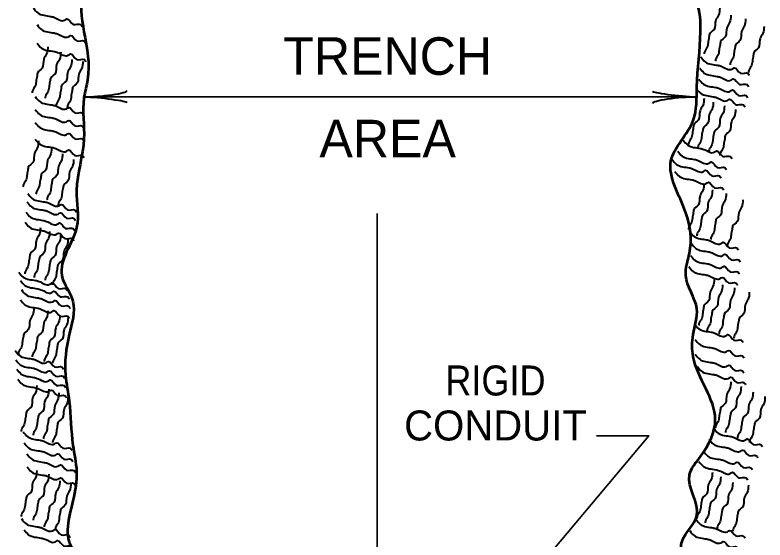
# Model space of a CAD drawing. Extents: x -617 to 238, y 23 to 567.
# Drawn here: x -260.3 to -200.2, y 290.5 to 332.5 of the extents above; entities that cross this region are included whole.
import ezdxf
from ezdxf.enums import TextEntityAlignment as Align

# ---------------------------------------------------------------- set-up
doc = ezdxf.new("R2010")
doc.units = 0
doc.header["$LTSCALE"] = 0.96
doc.layers.add('1', color=7, linetype='Continuous', lineweight=40)

msp = doc.modelspace()

# ---------------------------------------------------------------- linework, layer by layer
at = {"layer": '1', "lineweight": 35}
for p, q in [((-205.7838, 325.9777), (-254.7461, 325.9777)), ((-231.291, 269.4176), (-231.291, 316.6626))]:
    msp.add_line(p, q, dxfattribs=at)
msp.add_lwpolyline([(-224.4112, 281.1268), (-209.5319, 298.8592), (-213.7319, 298.8592)], dxfattribs=at)
at = {"layer": '1'}
for centre, major_axis, ratio, start_param, end_param in [((-253.4015, 325.7238), (2.1077, -0.2108), 0.07063, 6.2823074, 8.5597026), ((-253.4015, 325.7238), (2.1077, -0.2108), 0.07063, 6.2823074, 8.5597026), ((-253.4367, 326.3093), (-2.1428, -0.1874), 0.122415, 0.8963533, 3.1415927), ((-253.4367, 326.3093), (-2.1428, -0.1874), 0.122415, 0.8963533, 3.1415927), ((-207.0932, 325.6461), (2.1428, 0.1874), 0.122415, 0.8963533, 3.1415927), ((-207.1284, 326.2316), (2.1077, -0.2108), 0.07063, 3.1407148, 5.41811)]:
    msp.add_ellipse(centre, major_axis=major_axis, ratio=ratio, start_param=start_param, end_param=end_param, dxfattribs=at)
at = {"layer": '1', "lineweight": 53}
msp.add_spline([(-255.291, 382.6114), (-255.9281, 375.2243), (-254.7461, 372.2695), (-255.9281, 369.6102), (-255.0416, 367.2463), (-255.9281, 363.9961), (-254.7461, 361.9277), (-254.4506, 359.2684), (-254.7461, 355.1316), (-255.0416, 353.0633), (-256.2235, 351.5858), (-256.519, 350.6994), (-255.9281, 349.222), (-255.6326, 347.4491), (-255.3371, 345.3807), (-255.0416, 343.3124), (-255.0416, 340.9485), (-253.8597, 337.6982), (-254.1552, 335.6299), (-254.7461, 334.4479), (-254.7461, 331.1977), (-254.4506, 327.3564), (-254.7461, 325.879), (-254.7461, 322.6287), (-255.3371, 318.492), (-255.3371, 315.5372), (-256.519, 311.6959), (-255.6326, 309.6275), (-255.9281, 306.9682), (-256.2235, 303.7179), (-255.9281, 301.6495), (-255.6326, 298.1038), (-255.3371, 296.0354), (-255.6326, 293.6716), (-255.6326, 289.8303), (-254.7461, 288.9439), (-255.3371, 284.2162), (-255.3371, 281.5568), (-255.0416, 279.7839), (-255.6326, 276.2382), (-255.0416, 274.7608), (-255.6326, 272.1014), (-255.0416, 270.9195), (-252.6778, 268.5557), (-250.6094, 269.1466), (-248.541, 270.624), (-246.7681, 269.1466), (-244.9953, 268.8511), (-241.154, 268.8511), (-237.3127, 270.3286), (-236.1308, 269.4421), (-231.1076, 269.4421), (-226.6754, 270.0331), (-224.3116, 269.4421), (-219.2884, 270.0331), (-217.5155, 269.7376), (-212.1969, 270.0331), (-211.6059, 269.1466), (-208.0601, 269.7376), (-205.4008, 273.2834), (-205.6963, 275.3517), (-205.9918, 276.5337), (-207.7646, 282.1478), (-205.4008, 285.9891), (-206.8782, 289.2393), (-206.8782, 290.4213), (-205.6963, 292.4896), (-206.2872, 295.7399), (-205.4008, 297.2173), (-204.2189, 300.1721), (-205.9918, 305.1953), (-205.9918, 306.9682), (-205.6963, 309.0366), (-206.5827, 311.6959), (-206.2872, 313.4688), (-206.5827, 316.7191), (-207.7646, 320.8558), (-205.9918, 324.1061), (-205.6963, 326.7654), (-205.4008, 331.1977), (-205.6963, 333.5615), (-206.5827, 335.6299), (-206.5827, 337.4028), (-206.2872, 340.9485), (-207.4692, 344.4943), (-207.7646, 347.7446), (-205.6963, 350.9949), (-206.5827, 353.3587), (-206.8782, 354.8361), (-205.4008, 358.3819), (-206.5827, 361.0412), (-206.5827, 366.0644), (-206.2872, 367.8373), (-205.9918, 369.6102), (-207.1737, 372.8605), (-207.4692, 374.6334), (-207.291, 382.6114)], degree=3, dxfattribs=at)
at = {"layer": '1'}
for points in [[(-258.7864, 333.0944), (-258.4349, 332.6941), (-257.4359, 332.4265), (-257.1505, 332.3501), (-256.2943, 332.1206), (-256.1133, 332.2251), (-255.6188, 331.7868), (-255.0099, 331.7764), (-254.9054, 331.5956)], [(-203.8613, 333.1016), (-203.9639, 332.5197), (-204.1863, 332.1089), (-204.3146, 331.3813), (-204.6827, 330.9962), (-204.7082, 330.8508), (-204.7852, 330.4142), (-204.8621, 329.9777), (-205.0847, 329.567), (-205.1104, 329.4214)], [(-202.9749, 332.5107), (-203.0775, 331.9288), (-203.2999, 331.518), (-203.4282, 330.7904), (-203.7963, 330.4053), (-203.8218, 330.2599), (-203.8988, 329.8233), (-203.9757, 329.3868), (-204.1983, 328.9761), (-204.224, 328.8305)], [(-201.7929, 332.2152), (-201.8955, 331.6333), (-202.1179, 331.2225), (-202.2462, 330.4949), (-202.6143, 330.1098), (-202.6398, 329.9644), (-202.7168, 329.5278), (-202.7937, 329.0913), (-203.0163, 328.6806), (-203.042, 328.535)], [(-258.4909, 331.7648), (-258.1394, 331.3645), (-257.1404, 331.0969), (-256.855, 331.0205), (-255.9988, 330.791), (-255.8178, 330.8955), (-255.3233, 330.4572), (-254.7144, 330.4468), (-254.6099, 330.266)], [(-200.3155, 331.6242), (-200.4181, 331.0423), (-200.6405, 330.6315), (-200.7688, 329.9039), (-201.1369, 329.5188), (-201.1624, 329.3734), (-201.2394, 328.9368), (-201.3163, 328.5003), (-201.5389, 328.0896), (-201.5646, 327.944)], [(-258.4909, 330.2873), (-258.1394, 329.887), (-257.1404, 329.6194), (-256.855, 329.543), (-255.9988, 329.3135), (-255.8178, 329.418), (-255.3233, 328.9797), (-254.7144, 328.9693), (-254.6099, 328.7885)], [(-257.6388, 329.9989), (-257.7414, 329.417), (-257.9638, 329.0062), (-258.0921, 328.2786), (-258.4602, 327.8935), (-258.4857, 327.7481), (-258.5627, 327.3115), (-258.6396, 326.875), (-258.8622, 326.4643), (-258.8879, 326.3187)], [(-256.6047, 329.5557), (-256.7073, 328.9738), (-256.9297, 328.563), (-257.058, 327.8354), (-257.4261, 327.4503), (-257.4516, 327.3049), (-257.5286, 326.8683), (-257.6055, 326.4318), (-257.8281, 326.0211), (-257.8538, 325.8755)], [(-255.7183, 328.9647), (-255.8209, 328.3828), (-256.0433, 327.972), (-256.1716, 327.2444), (-256.5397, 326.8593), (-256.5652, 326.7139), (-256.6422, 326.2773), (-256.7191, 325.8408), (-256.9417, 325.4301), (-256.9674, 325.2845)], [(-205.3782, 329.1793), (-205.0267, 328.779), (-204.0277, 328.5114), (-203.7423, 328.435), (-202.8861, 328.2055), (-202.7051, 328.31), (-202.2106, 327.8717), (-201.6017, 327.8613), (-201.4972, 327.6805)], [(-254.8318, 328.817), (-254.9344, 328.2351), (-255.1568, 327.8243), (-255.2851, 327.0967), (-255.6532, 326.7116), (-255.6787, 326.5662), (-255.7557, 326.1296), (-255.8326, 325.6931), (-256.0552, 325.2824), (-256.0809, 325.1368)], [(-205.452, 328.2928), (-205.1005, 327.8925), (-204.1015, 327.6249), (-203.8161, 327.5485), (-202.9599, 327.319), (-202.7789, 327.4235), (-202.2844, 326.9852), (-201.6755, 326.9748), (-201.571, 326.794)], [(-205.5259, 327.4064), (-205.1744, 327.0061), (-204.1754, 326.7385), (-203.89, 326.6621), (-203.0338, 326.4326), (-202.8528, 326.5371), (-202.3583, 326.0988), (-201.7494, 326.0884), (-201.6449, 325.9076)], [(-205.7475, 326.6677), (-205.396, 326.2674), (-204.397, 325.9998), (-204.1116, 325.9234), (-203.2554, 325.6939), (-203.0744, 325.7984), (-202.5799, 325.3601), (-201.971, 325.3497), (-201.8665, 325.1689)], [(-258.6386, 326.0029), (-258.2871, 325.6026), (-257.2881, 325.335), (-257.0027, 325.2586), (-256.1465, 325.0291), (-255.9655, 325.1336), (-255.471, 324.6953), (-254.8621, 324.6849), (-254.7576, 324.5041)], [(-205.1171, 325.8623), (-205.2197, 325.2804), (-205.4421, 324.8696), (-205.5704, 324.142), (-205.9385, 323.7569), (-205.964, 323.6115), (-206.041, 323.1749), (-206.1179, 322.7384), (-206.3405, 322.3277), (-206.3662, 322.1821)], [(-204.3784, 325.5669), (-204.481, 324.985), (-204.7034, 324.5742), (-204.8317, 323.8466), (-205.1998, 323.4615), (-205.2253, 323.3161), (-205.3023, 322.8795), (-205.3792, 322.443), (-205.6018, 322.0323), (-205.6275, 321.8867)], [(-258.6386, 324.9687), (-258.2871, 324.5684), (-257.2881, 324.3008), (-257.0027, 324.2244), (-256.1465, 323.9949), (-255.9655, 324.0994), (-255.471, 323.6611), (-254.8621, 323.6507), (-254.7576, 323.4699)], [(-203.492, 325.2714), (-203.5946, 324.6895), (-203.817, 324.2787), (-203.9453, 323.5511), (-204.3134, 323.166), (-204.3389, 323.0206), (-204.4159, 322.584), (-204.4928, 322.1475), (-204.7154, 321.7368), (-204.7411, 321.5912)], [(-202.6055, 324.9759), (-202.7081, 324.394), (-202.9305, 323.9832), (-203.0588, 323.2556), (-203.4269, 322.8705), (-203.4524, 322.7251), (-203.5294, 322.2885), (-203.6063, 321.852), (-203.8289, 321.4413), (-203.8546, 321.2957)], [(-258.6386, 323.9345), (-258.2871, 323.5342), (-257.2881, 323.2666), (-257.0027, 323.1902), (-256.1465, 322.9607), (-255.9655, 323.0652), (-255.471, 322.6269), (-254.8621, 322.6165), (-254.7576, 322.4357)], [(-258.3776, 322.4641), (-258.4802, 321.8822), (-258.7026, 321.4714), (-258.8309, 320.7438), (-259.199, 320.3587), (-259.2245, 320.2133), (-259.3015, 319.7767), (-259.3784, 319.3402), (-259.601, 318.9295), (-259.6267, 318.7839)], [(-258.6386, 322.6048), (-258.2871, 322.2045), (-257.2881, 321.9369), (-257.0027, 321.8605), (-256.1465, 321.631), (-255.9655, 321.7355), (-255.471, 321.2972), (-254.8621, 321.2868), (-254.7576, 321.106)], [(-206.7816, 322.531), (-206.4301, 322.1307), (-205.4311, 321.8631), (-205.1457, 321.7867), (-204.2895, 321.5572), (-204.1085, 321.6617), (-203.614, 321.2234), (-203.0051, 321.213), (-202.9006, 321.0322)], [(-257.3434, 321.8732), (-257.446, 321.2913), (-257.6684, 320.8805), (-257.7967, 320.1529), (-258.1648, 319.7678), (-258.1903, 319.6224), (-258.2673, 319.1858), (-258.3442, 318.7493), (-258.5668, 318.3386), (-258.5925, 318.193)], [(-256.457, 321.4299), (-256.5596, 320.848), (-256.782, 320.4372), (-256.9103, 319.7096), (-257.2784, 319.3245), (-257.3039, 319.1791), (-257.3809, 318.7425), (-257.4578, 318.306), (-257.6804, 317.8953), (-257.7061, 317.7497)], [(-207.2248, 321.6445), (-206.8733, 321.2442), (-205.8743, 320.9766), (-205.5889, 320.9002), (-204.7327, 320.6707), (-204.5517, 320.7752), (-204.0572, 320.3369), (-203.4483, 320.3265), (-203.3438, 320.1457)], [(-255.5705, 320.9867), (-255.6731, 320.4048), (-255.8955, 319.994), (-256.0238, 319.2664), (-256.3919, 318.8813), (-256.4174, 318.7359), (-256.4944, 318.2993), (-256.5713, 317.8628), (-256.7939, 317.4521), (-256.8196, 317.3065)], [(-207.668, 320.9797), (-207.3165, 320.5794), (-206.3175, 320.3118), (-206.0321, 320.2354), (-205.1759, 320.0059), (-204.9949, 320.1104), (-204.5004, 319.6721), (-203.8915, 319.6617), (-203.787, 319.4809)], [(-207.4464, 320.0194), (-207.0949, 319.6191), (-206.0959, 319.3515), (-205.8105, 319.2751), (-204.9543, 319.0456), (-204.7733, 319.1501), (-204.2788, 318.7118), (-203.6699, 318.7014), (-203.5654, 318.5206)], [(-205.1172, 319.0663), (-205.2198, 318.4844), (-205.4422, 318.0736), (-205.5705, 317.346), (-205.9386, 316.9609), (-205.9641, 316.8155), (-206.0411, 316.3789), (-206.118, 315.9424), (-206.3406, 315.5317), (-206.3663, 315.3861)], [(-259.2296, 318.2464), (-258.8781, 317.8461), (-257.8791, 317.5785), (-257.5937, 317.5021), (-256.7375, 317.2726), (-256.5565, 317.3771), (-256.062, 316.9388), (-255.4531, 316.9284), (-255.3486, 316.7476)], [(-204.4524, 318.5492), (-204.555, 317.9673), (-204.7774, 317.5565), (-204.9057, 316.8289), (-205.2738, 316.4438), (-205.2993, 316.2984), (-205.3763, 315.8618), (-205.4532, 315.4253), (-205.6758, 315.0146), (-205.7015, 314.869)], [(-203.3443, 318.2537), (-203.4469, 317.6718), (-203.6693, 317.261), (-203.7976, 316.5334), (-204.1657, 316.1483), (-204.1912, 316.0029), (-204.2682, 315.5663), (-204.3451, 315.1298), (-204.5677, 314.7191), (-204.5934, 314.5735)], [(-259.3035, 317.5816), (-258.952, 317.1813), (-257.953, 316.9137), (-257.6676, 316.8373), (-256.8114, 316.6078), (-256.6304, 316.7123), (-256.1359, 316.274), (-255.527, 316.2636), (-255.4225, 316.0828)], [(-202.0147, 317.7366), (-202.1173, 317.1547), (-202.3397, 316.7439), (-202.468, 316.0163), (-202.8361, 315.6312), (-202.8616, 315.4858), (-202.9386, 315.0492), (-203.0155, 314.6127), (-203.2381, 314.202), (-203.2638, 314.0564)], [(-259.3773, 316.769), (-259.0258, 316.3687), (-258.0268, 316.1011), (-257.7414, 316.0247), (-256.8852, 315.7952), (-256.7042, 315.8997), (-256.2097, 315.4614), (-255.6008, 315.451), (-255.4963, 315.2702)], [(-259.4512, 315.9565), (-259.0997, 315.5562), (-258.1007, 315.2886), (-257.8153, 315.2122), (-256.9591, 314.9827), (-256.7781, 315.0872), (-256.2836, 314.6489), (-255.6747, 314.6385), (-255.5702, 314.4577)], [(-258.2299, 315.5203), (-258.3325, 314.9384), (-258.5549, 314.5276), (-258.6832, 313.8), (-259.0513, 313.4149), (-259.0768, 313.2695), (-259.1538, 312.8329), (-259.2307, 312.3964), (-259.4533, 311.9857), (-259.479, 311.8401)], [(-257.4912, 315.2248), (-257.5938, 314.6429), (-257.8162, 314.2321), (-257.9445, 313.5045), (-258.3126, 313.1194), (-258.3381, 312.974), (-258.4151, 312.5374), (-258.492, 312.1009), (-258.7146, 311.6902), (-258.7403, 311.5446)], [(-206.2646, 315.2178), (-205.9131, 314.8175), (-204.9141, 314.5499), (-204.6287, 314.4735), (-203.7725, 314.244), (-203.5915, 314.3485), (-203.097, 313.9102), (-202.4881, 313.8998), (-202.3836, 313.719)], [(-256.6047, 315.0032), (-256.7073, 314.4213), (-256.9297, 314.0105), (-257.058, 313.2829), (-257.4261, 312.8978), (-257.4516, 312.7524), (-257.5286, 312.3158), (-257.6055, 311.8793), (-257.8281, 311.4686), (-257.8538, 311.323)], [(-256.0137, 314.6338), (-256.1163, 314.0519), (-256.3387, 313.6411), (-256.467, 312.9135), (-256.8351, 312.5284), (-256.8606, 312.383), (-256.9376, 311.9464), (-257.0145, 311.5099), (-257.2371, 311.0992), (-257.2628, 310.9536)], [(-206.1168, 314.2575), (-205.7653, 313.8572), (-204.7663, 313.5896), (-204.4809, 313.5132), (-203.6247, 313.2837), (-203.4437, 313.3882), (-202.9492, 312.9499), (-202.3403, 312.9395), (-202.2358, 312.7587)], [(-206.1907, 313.2971), (-205.8392, 312.8968), (-204.8402, 312.6292), (-204.5548, 312.5528), (-203.6986, 312.3233), (-203.5176, 312.4278), (-203.0231, 311.9895), (-202.4142, 311.9791), (-202.3097, 311.7983)], [(-206.3384, 312.4107), (-205.9869, 312.0104), (-204.9879, 311.7428), (-204.7025, 311.6664), (-203.8463, 311.4369), (-203.6653, 311.5414), (-203.1708, 311.1031), (-202.5619, 311.0927), (-202.4574, 310.9119)], [(-259.9683, 311.9675), (-259.6168, 311.5672), (-258.6178, 311.2996), (-258.3324, 311.2232), (-257.4762, 310.9937), (-257.2952, 311.0982), (-256.8007, 310.6599), (-256.1918, 310.6495), (-256.0873, 310.4687)], [(-259.8206, 311.3027), (-259.4691, 310.9024), (-258.4701, 310.6348), (-258.1847, 310.5584), (-257.3285, 310.3289), (-257.1475, 310.4334), (-256.653, 309.9951), (-256.0441, 309.9847), (-255.9396, 309.8039)], [(-204.3046, 311.3837), (-204.4072, 310.8018), (-204.6296, 310.391), (-204.7579, 309.6634), (-205.126, 309.2783), (-205.1515, 309.1329), (-205.2285, 308.6963), (-205.3054, 308.2598), (-205.528, 307.8491), (-205.5537, 307.7035)], [(-203.6398, 310.9405), (-203.7424, 310.3586), (-203.9648, 309.9478), (-204.0931, 309.2202), (-204.4612, 308.8351), (-204.4867, 308.6897), (-204.5637, 308.2531), (-204.6406, 307.8166), (-204.8632, 307.4059), (-204.8889, 307.2603)], [(-259.7467, 310.564), (-259.3952, 310.1637), (-258.3962, 309.8961), (-258.1108, 309.8197), (-257.2546, 309.5902), (-257.0736, 309.6947), (-256.5791, 309.2564), (-255.9702, 309.246), (-255.8657, 309.0652)], [(-202.6794, 310.7189), (-202.782, 310.137), (-203.0044, 309.7262), (-203.1327, 308.9986), (-203.5008, 308.6135), (-203.5263, 308.4681), (-203.6033, 308.0315), (-203.6802, 307.595), (-203.9028, 307.1843), (-203.9285, 307.0387)], [(-201.4975, 310.3495), (-201.6001, 309.7676), (-201.8225, 309.3568), (-201.9508, 308.6292), (-202.3189, 308.2441), (-202.3444, 308.0987), (-202.4214, 307.6621), (-202.4983, 307.2256), (-202.7209, 306.8149), (-202.7466, 306.6693)], [(-259.8206, 309.7514), (-259.4691, 309.3511), (-258.4701, 309.0835), (-258.1847, 309.0071), (-257.3285, 308.7776), (-257.1475, 308.8821), (-256.653, 308.4438), (-256.0441, 308.4334), (-255.9396, 308.2526)], [(-258.747, 309.0936), (-258.8496, 308.5117), (-259.072, 308.1009), (-259.2003, 307.3733), (-259.5684, 306.9882), (-259.5939, 306.8428), (-259.6709, 306.4062), (-259.7478, 305.9697), (-259.9704, 305.559), (-259.9961, 305.4134)], [(-257.6389, 308.872), (-257.7415, 308.2901), (-257.9639, 307.8793), (-258.0922, 307.1517), (-258.4603, 306.7666), (-258.4858, 306.6212), (-258.5628, 306.1846), (-258.6397, 305.7481), (-258.8623, 305.3374), (-258.888, 305.1918)], [(-256.6786, 308.5027), (-256.7812, 307.9208), (-257.0036, 307.51), (-257.1319, 306.7824), (-257.5, 306.3973), (-257.5255, 306.2519), (-257.6025, 305.8153), (-257.6794, 305.3788), (-257.902, 304.9681), (-257.9277, 304.8225)], [(-256.0138, 308.3549), (-256.1164, 307.773), (-256.3388, 307.3622), (-256.4671, 306.6346), (-256.8352, 306.2495), (-256.8607, 306.1041), (-256.9377, 305.6675), (-257.0146, 305.231), (-257.2372, 304.8203), (-257.2629, 304.6747)], [(-205.8952, 307.8307), (-205.5437, 307.4304), (-204.5447, 307.1628), (-204.2593, 307.0864), (-203.4031, 306.8569), (-203.2221, 306.9614), (-202.7276, 306.5231), (-202.1187, 306.5127), (-202.0142, 306.3319)], [(-205.8214, 306.5749), (-205.4699, 306.1746), (-204.4709, 305.907), (-204.1855, 305.8306), (-203.3293, 305.6011), (-203.1483, 305.7056), (-202.6538, 305.2673), (-202.0449, 305.2569), (-201.9404, 305.0761)], [(-260.2637, 305.6885), (-259.9122, 305.2882), (-258.9132, 305.0206), (-258.6278, 304.9442), (-257.7716, 304.7147), (-257.5906, 304.8192), (-257.0961, 304.3809), (-256.4872, 304.3705), (-256.3827, 304.1897)], [(-260.1899, 304.9498), (-259.8384, 304.5495), (-258.8394, 304.2819), (-258.554, 304.2055), (-257.6978, 303.976), (-257.5168, 304.0805), (-257.0223, 303.6422), (-256.4134, 303.6318), (-256.3089, 303.451)], [(-205.8214, 305.393), (-205.4699, 304.9927), (-204.4709, 304.7251), (-204.1855, 304.6487), (-203.3293, 304.4192), (-203.1483, 304.5237), (-202.6538, 304.0854), (-202.0449, 304.075), (-201.9404, 303.8942)], [(-205.6736, 304.4327), (-205.3221, 304.0324), (-204.3231, 303.7648), (-204.0377, 303.6884), (-203.1815, 303.4589), (-203.0005, 303.5634), (-202.506, 303.1251), (-201.8971, 303.1147), (-201.7926, 302.9339)], [(-260.116, 304.2111), (-259.7645, 303.8108), (-258.7655, 303.5432), (-258.4801, 303.4668), (-257.6239, 303.2373), (-257.4429, 303.3418), (-256.9484, 302.9035), (-256.3395, 302.8931), (-256.235, 302.7123)], [(-260.0421, 303.3985), (-259.6906, 302.9982), (-258.6916, 302.7306), (-258.4062, 302.6542), (-257.55, 302.4247), (-257.369, 302.5292), (-256.8745, 302.0909), (-256.2656, 302.0805), (-256.1611, 301.8997)], [(-202.9749, 303.1841), (-203.0775, 302.6022), (-203.2999, 302.1914), (-203.4282, 301.4638), (-203.7963, 301.0787), (-203.8218, 300.9333), (-203.8988, 300.4967), (-203.9757, 300.0602), (-204.1983, 299.6495), (-204.224, 299.5039)], [(-258.5253, 302.8885), (-258.6279, 302.3066), (-258.8503, 301.8958), (-258.9786, 301.1682), (-259.3467, 300.7831), (-259.3722, 300.6377), (-259.4492, 300.2011), (-259.5261, 299.7646), (-259.7487, 299.3539), (-259.7744, 299.2083)], [(-257.565, 302.593), (-257.6676, 302.0111), (-257.89, 301.6003), (-258.0183, 300.8727), (-258.3864, 300.4876), (-258.4119, 300.3422), (-258.4889, 299.9056), (-258.5658, 299.4691), (-258.7884, 299.0584), (-258.8141, 298.9128)], [(-202.1623, 302.8148), (-202.2649, 302.2329), (-202.4873, 301.8221), (-202.6156, 301.0945), (-202.9837, 300.7094), (-203.0092, 300.564), (-203.0862, 300.1274), (-203.1631, 299.6909), (-203.3857, 299.2802), (-203.4114, 299.1346)], [(-256.7524, 302.2975), (-256.855, 301.7156), (-257.0774, 301.3048), (-257.2057, 300.5772), (-257.5738, 300.1921), (-257.5993, 300.0467), (-257.6763, 299.6101), (-257.7532, 299.1736), (-257.9758, 298.7629), (-258.0015, 298.6173)], [(-256.0137, 302.002), (-256.1163, 301.4201), (-256.3387, 301.0093), (-256.467, 300.2817), (-256.8351, 299.8966), (-256.8606, 299.7512), (-256.9376, 299.3146), (-257.0145, 298.8781), (-257.2371, 298.4674), (-257.2628, 298.3218)], [(-201.202, 302.3716), (-201.3046, 301.7897), (-201.527, 301.3789), (-201.6553, 300.6513), (-202.0234, 300.2662), (-202.0489, 300.1208), (-202.1259, 299.6842), (-202.2028, 299.2477), (-202.4254, 298.837), (-202.4511, 298.6914)], [(-200.2417, 302.0022), (-200.3443, 301.4203), (-200.5667, 301.0095), (-200.695, 300.2819), (-201.0631, 299.8968), (-201.0886, 299.7514), (-201.1656, 299.3148), (-201.2425, 298.8783), (-201.4651, 298.4676), (-201.4908, 298.322)], [(-259.599, 299.1879), (-259.2475, 298.7876), (-258.2485, 298.52), (-257.9631, 298.4436), (-257.1069, 298.2141), (-256.9259, 298.3186), (-256.4314, 297.8803), (-255.8225, 297.8699), (-255.718, 297.6891)], [(-204.344, 299.4834), (-203.9925, 299.0831), (-202.9935, 298.8155), (-202.7081, 298.7391), (-201.8519, 298.5096), (-201.6709, 298.6141), (-201.1764, 298.1758), (-200.5675, 298.1654), (-200.463, 297.9846)], [(-204.7133, 298.597), (-204.3618, 298.1967), (-203.3628, 297.9291), (-203.0774, 297.8527), (-202.2212, 297.6232), (-202.0402, 297.7277), (-201.5457, 297.2894), (-200.9368, 297.279), (-200.8323, 297.0982)], [(-259.5251, 298.3015), (-259.1736, 297.9012), (-258.1746, 297.6336), (-257.8892, 297.5572), (-257.033, 297.3277), (-256.852, 297.4322), (-256.3575, 296.9939), (-255.7486, 296.9835), (-255.6441, 296.8027)], [(-259.3035, 297.415), (-258.952, 297.0147), (-257.953, 296.7471), (-257.6676, 296.6707), (-256.8114, 296.4412), (-256.6304, 296.5457), (-256.1359, 296.1074), (-255.527, 296.097), (-255.4225, 295.9162)], [(-205.1565, 297.6366), (-204.805, 297.2363), (-203.806, 296.9687), (-203.5206, 296.8923), (-202.6644, 296.6628), (-202.4834, 296.7673), (-201.9889, 296.329), (-201.38, 296.3186), (-201.2755, 296.1378)], [(-205.5259, 296.8241), (-205.1744, 296.4238), (-204.1754, 296.1562), (-203.89, 296.0798), (-203.0338, 295.8503), (-202.8528, 295.9548), (-202.3583, 295.5165), (-201.7494, 295.5061), (-201.6449, 295.3253)], [(-258.5254, 296.0924), (-258.628, 295.5105), (-258.8504, 295.0997), (-258.9787, 294.3721), (-259.3468, 293.987), (-259.3723, 293.8416), (-259.4493, 293.405), (-259.5262, 292.9685), (-259.7488, 292.5578), (-259.7745, 292.4122)], [(-259.3035, 296.3809), (-258.952, 295.9806), (-257.953, 295.713), (-257.6676, 295.6366), (-256.8114, 295.4071), (-256.6304, 295.5116), (-256.1359, 295.0733), (-255.527, 295.0629), (-255.4225, 294.8821)], [(-204.4522, 295.9447), (-204.5548, 295.3628), (-204.7772, 294.952), (-204.9055, 294.2244), (-205.2736, 293.8393), (-205.2991, 293.6939), (-205.3761, 293.2573), (-205.453, 292.8208), (-205.6756, 292.4101), (-205.7013, 292.2645)], [(-257.5651, 295.7969), (-257.6677, 295.215), (-257.8901, 294.8042), (-258.0184, 294.0766), (-258.3865, 293.6915), (-258.412, 293.5461), (-258.489, 293.1095), (-258.5659, 292.673), (-258.7885, 292.2623), (-258.8142, 292.1167)], [(-203.7874, 295.5754), (-203.89, 294.9935), (-204.1124, 294.5827), (-204.2407, 293.8551), (-204.6088, 293.47), (-204.6343, 293.3246), (-204.7113, 292.888), (-204.7882, 292.4515), (-205.0108, 292.0408), (-205.0365, 291.8952)], [(-256.6786, 295.2798), (-256.7812, 294.6979), (-257.0036, 294.2871), (-257.1319, 293.5595), (-257.5, 293.1744), (-257.5255, 293.029), (-257.6025, 292.5924), (-257.6794, 292.1559), (-257.902, 291.7452), (-257.9277, 291.5996)], [(-255.7922, 295.0582), (-255.8948, 294.4763), (-256.1172, 294.0655), (-256.2455, 293.3379), (-256.6136, 292.9528), (-256.6391, 292.8074), (-256.7161, 292.3708), (-256.793, 291.9343), (-257.0156, 291.5236), (-257.0413, 291.378)], [(-202.8271, 295.1321), (-202.9297, 294.5502), (-203.1521, 294.1394), (-203.2804, 293.4118), (-203.6485, 293.0267), (-203.674, 292.8813), (-203.751, 292.4447), (-203.8279, 292.0082), (-204.0505, 291.5975), (-204.0762, 291.4519)], [(-201.5713, 294.9105), (-201.6739, 294.3286), (-201.8963, 293.9178), (-202.0246, 293.1902), (-202.3927, 292.8051), (-202.4182, 292.6597), (-202.4952, 292.2231), (-202.5721, 291.7866), (-202.7947, 291.3759), (-202.8204, 291.2303)], [(-259.7467, 292.2441), (-259.3952, 291.8438), (-258.3962, 291.5762), (-258.1108, 291.4998), (-257.2546, 291.2703), (-257.0736, 291.3748), (-256.5791, 290.9365), (-255.9702, 290.9261), (-255.8657, 290.7453)], [(-205.7474, 292.1702), (-205.3959, 291.7699), (-204.3969, 291.5023), (-204.1115, 291.4259), (-203.2553, 291.1964), (-203.0743, 291.3009), (-202.5798, 290.8626), (-201.9709, 290.8522), (-201.8664, 290.6714)], [(-259.5251, 291.3576), (-259.1736, 290.9573), (-258.1746, 290.6897), (-257.8892, 290.6133), (-257.033, 290.3838), (-256.852, 290.4883), (-256.3575, 290.05), (-255.7486, 290.0396), (-255.6441, 289.8588)], [(-206.2645, 291.2838), (-205.913, 290.8835), (-204.914, 290.6159), (-204.6286, 290.5395), (-203.7724, 290.31), (-203.5914, 290.4145), (-203.0969, 289.9762), (-202.488, 289.9658), (-202.3835, 289.785)]]:
    msp.add_spline(points, degree=3, dxfattribs=at)

# ---------------------------------------------------------------- texts
for s, height, p in [('TRENCH', 3, (-230.4395, 327.7496)), ('AREA', 3, (-230.4395, 321.1496)), ('CONDUIT', 2.4, (-221.8132, 298.4953))]:
    msp.add_text(s, height=height, dxfattribs=at).set_placement(p, align=Align.CENTER)
at = {"layer": '1', "width": 0.9}
msp.add_text('RIGID', height=2.4, dxfattribs=at).set_placement((-221.8132, 302.0953), align=Align.CENTER)

doc.saveas('drawing.dxf')
